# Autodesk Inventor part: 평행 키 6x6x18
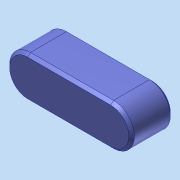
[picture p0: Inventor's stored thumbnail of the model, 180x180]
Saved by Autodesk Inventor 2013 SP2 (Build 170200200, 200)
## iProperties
Created: 2026-01
Part Number: 평행 키 6x6x18
Material: Generic
Document SubType Name: Modeling
Designer: a
Density: 1 g/cm^3
Author: a
변환 표준: STEP AP214IS
전처리기: Build: 200, Release: 2013 SP2 Update 6 - Date: Thu 07/17/2014
전송 단위: 밀리미터
불확실성: 0.01
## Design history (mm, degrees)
node "평행 키 6x6x181"
body "Solid1"
node "기준1"
